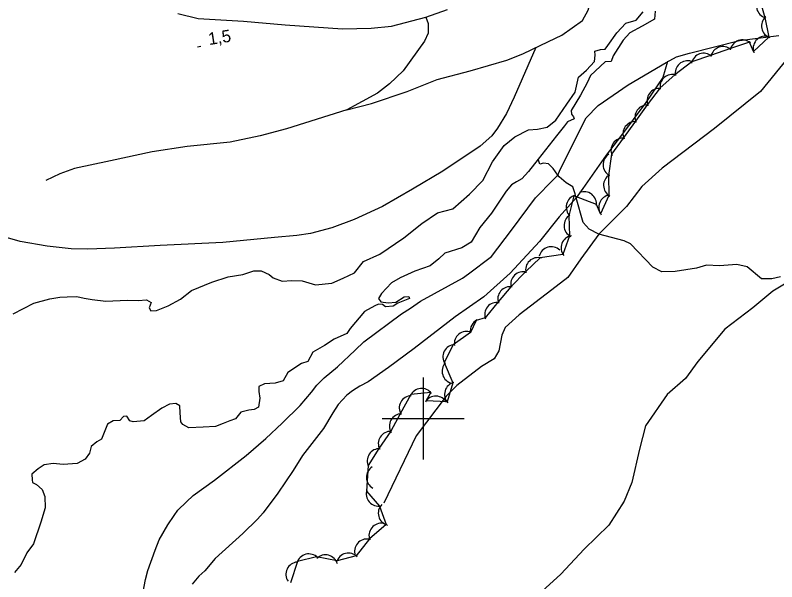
# Model space of a CAD drawing. Extents: x 643342 to 646936, y 5873857 to 5876103.
# Drawn here: x 644900.4 to 645086.4, y 5874560.2 to 5874698.4 of the extents above; entities that cross this region are included whole.
import ezdxf

# ---------------------------------------------------------------- set-up
doc = ezdxf.new("R2010")
doc.units = 0
for name, color, linetype in [('Niveau 2', 7, 'Continuous'), ('Niveau 22', 7, 'Continuous'), ('Niveau 3', 7, 'Continuous'), ('Niveau 4', 7, 'Continuous'), ('Niveau 44', 7, 'Continuous'), ('Niveau 61', 7, 'Continuous')]:
    doc.layers.add(name, color=color, linetype=linetype)

msp = doc.modelspace()

# ---------------------------------------------------------------- linework, layer by layer
at = {"layer": 'Niveau 2'}
for points in [[(645090.92, 5874634.41), (645085.43, 5874631.02), (645080.51, 5874627.01), (645073.66, 5874621.81), (645067.12, 5874613.9), (645064.04, 5874609.72), (645059.64, 5874605.87), (645054.32, 5874598.16), (645052.83, 5874592.48), (645050.96, 5874584.41), (645049.1, 5874579.78), (645045.36, 5874573.95), (645039.33, 5874568.09), (645033.6, 5874562.02)], [(645033.6, 5874562.02), (645028.16, 5874557.02), (645017.36, 5874550.84), (645003.58, 5874543.28), (644999.48, 5874539.32), (644990.35, 5874529.34), (644978.11, 5874518.31), (644963.38, 5874509.01), (644955.88, 5874501.15), (644949.79, 5874495.17), (644945.06, 5874485), (644942.13, 5874477.8), (644934.92, 5874462.37), (644928.86, 5874454.37), (644919.76, 5874449.01), (644910.52, 5874442.33), (644902.84, 5874436.11), (644893.32, 5874425.03), (644885.55, 5874412.64)]]:
    msp.add_lwpolyline(points, dxfattribs=at)
at = {"layer": 'Niveau 22'}
for points in [[(644981.35, 5874675.34), (644987.4, 5874676.81), (644996.09, 5874679.76), (645003.46, 5874682.74), (645011.49, 5874684.81), (645020.42, 5874687.42), (645024.34, 5874688.99), (645030.61, 5874691.98), (645033.85, 5874693.53), (645038.93, 5874697.08), (645040.29, 5874699.66), (645043.22, 5874710.44), (645044.35, 5874714.56)], [(644940.11, 5874698.83), (644945.06, 5874697.6), (644956.14, 5874696.9), (644966.28, 5874696.01), (644980.33, 5874695.03), (644987.31, 5874695.25), (644992.25, 5874695.69), (645000.63, 5874697.9), (645005.95, 5874699.8)], [(645000.63, 5874697.9), (645001.21, 5874696.39), (645001.25, 5874694.02), (645000.32, 5874692.05), (644995.14, 5874684.81), (644991.81, 5874681.62), (644988.88, 5874679.4), (644981.35, 5874675.34), (644966.62, 5874670.68), (644960.22, 5874668.96), (644952.86, 5874667.4), (644942.37, 5874666.35), (644933.8, 5874665.08), (644923.64, 5874662.86), (644914.87, 5874660.98), (644911.28, 5874659.67), (644907.84, 5874658.08)], [(645092.22, 5874694.56), (645088.79, 5874687.68), (645082.36, 5874679.78), (645071.16, 5874670.72), (645058.35, 5874661.09), (645053.45, 5874656.6), (645049.65, 5874651.72), (645042.92, 5874644.95), (645038.48, 5874638.96), (645035.37, 5874634.36), (645031.44, 5874631.36), (645023.46, 5874625.25), (645020.01, 5874622.17), (645019.19, 5874620.33), (645018.51, 5874616.49), (645017.34, 5874614.51), (645014.28, 5874612.64), (645008.2, 5874608.08), (645005.67, 5874605.41), (644998.28, 5874595.77), (644990.43, 5874579.33)], [(644937.65, 5874574.06), (644939.2, 5874576.29), (644940.07, 5874577.64), (644942.18, 5874579.62), (644943.83, 5874581.17), (644949.04, 5874584.91), (644956.82, 5874590.97), (644961.6, 5874595.12), (644965.58, 5874598.86), (644969.96, 5874603.18), (644972.75, 5874606.39), (644974.04, 5874608.12), (644975.85, 5874609.88), (644979.07, 5874612.6), (644983.39, 5874616.68), (644985.53, 5874618.72), (644994.74, 5874625.51), (644996.94, 5874626.91), (644999.35, 5874628.58), (645009.64, 5874634.23), (645011.09, 5874635.25), (645016.72, 5874639.54), (645021.6, 5874645.93), (645027.45, 5874653.81), (645031.76, 5874658.25), (645032.87, 5874659.4), (645033.3, 5874660.32), (645034.96, 5874663.64), (645039.85, 5874673.36), (645042.72, 5874676.4), (645050.07, 5874681.4), (645059.39, 5874686.89), (645061.9, 5874688.24), (645065.03, 5874689.16), (645077.23, 5874692.22), (645086.84, 5874693.44)], [(645027.55, 5874690.52), (645022.26, 5874678.41), (645020.33, 5874674.42), (645018.17, 5874670.81), (645016.75, 5874668.93), (645013.91, 5874666.44), (645004.8, 5874660.3), (644997.4, 5874655.97), (644990.09, 5874651.75), (644983.19, 5874648.54), (644977.67, 5874646.52), (644972.49, 5874645.12), (644969.19, 5874644.65), (644963.73, 5874644.13), (644951.05, 5874642.96), (644935.79, 5874642.18), (644924.64, 5874641.52), (644918.08, 5874641.31), (644914.04, 5874641.39), (644908.2, 5874642.02), (644901.63, 5874643.18), (644889.88, 5874646.5)], [(645059.72, 5874687.06), (645058.57, 5874683.18), (645054.38, 5874677.08), (645048.2, 5874668.83), (645044.74, 5874664.21), (645039.02, 5874656.1), (645037.41, 5874653.84), (645033.24, 5874649.16), (645028.45, 5874643.14), (645021.29, 5874635.41), (645014.82, 5874629.64), (645007.82, 5874624.77), (644997.8, 5874617.08), (644991.58, 5874612.43), (644986.6, 5874608.9), (644984.52, 5874607.9), (644982.74, 5874606.78), (644981.35, 5874605.69), (644979.22, 5874603.42), (644977.95, 5874601.4), (644975.65, 5874597.54), (644970.52, 5874590.96), (644968.25, 5874587.29), (644964.5, 5874581.8), (644960.9, 5874576.95), (644959.55, 5874575.42), (644955.99, 5874571.91), (644949.24, 5874565.83), (644946.73, 5874562.84), (644945.21, 5874561.49), (644943.59, 5874559.6)], [(644898.02, 5874498.92), (644900.58, 5874503.83), (644903.98, 5874509.35), (644906.78, 5874514.43), (644908.44, 5874517.12), (644909.89, 5874519.24), (644916.01, 5874526.45), (644920.84, 5874532.57), (644922.72, 5874534.87), (644927.21, 5874539.05), (644928.41, 5874540.13), (644928.79, 5874540.94), (644929.33, 5874542.75), (644929.86, 5874545.4), (644930.55, 5874549.19), (644931.23, 5874555.58), (644932.21, 5874560.72), (644932.77, 5874562.92), (644934.55, 5874567.88), (644935.58, 5874570.37), (644937.65, 5874574.06)]]:
    msp.add_lwpolyline(points, dxfattribs=at)
at = {"layer": 'Niveau 3'}
msp.add_line((644944.91, 5874690.69), (644945.7, 5874690.82), dxfattribs=at)
at = {"layer": 'Niveau 4'}
for points in [[(645056.65, 5874699.37), (645056.54, 5874697.46), (645053.46, 5874695.71), (645050.5, 5874694.09), (645048.84, 5874692.32), (645046.39, 5874688.47), (645045.89, 5874687.12), (645044.47, 5874687.03), (645040.91, 5874683.7), (645040.09, 5874681.87), (645038.4, 5874678.9), (645036.17, 5874675.18), (645036.24, 5874674.24), (645036.76, 5874673.56), (645036.91, 5874673.09), (645035.3, 5874672.39), (645034.54, 5874671.39), (645032.57, 5874669), (645028.12, 5874663.23), (645025.72, 5874660.22), (645024.07, 5874658.44), (645022.81, 5874657.77), (645021.56, 5874656.97), (645020.25, 5874655.46)], [(645041.93, 5874689.6), (645043.32, 5874690.05), (645044.5, 5874690.13), (645045.15, 5874691), (645047.3, 5874694.12), (645049.51, 5874696.41), (645052.06, 5874697.17), (645053.7, 5874699.18)], [(644899.92, 5874625.49), (644904.97, 5874628.09), (644908.81, 5874629.17), (644911.27, 5874629.58), (644913.05, 5874629.69), (644915.42, 5874629.73), (644917.23, 5874629.37), (644919.15, 5874629.02), (644922.5, 5874628.65), (644927.71, 5874628.88), (644930.44, 5874628.82), (644932.45, 5874628.95), (644933.56, 5874628.31), (644933.06, 5874626.97), (644933.47, 5874626.28), (644934.89, 5874626.37), (644937.77, 5874627.52), (644940.74, 5874629.14), (644943.45, 5874631.23), (644948.41, 5874633.22), (644952.35, 5874634.55), (644955.99, 5874635.15), (644958.65, 5874636.04), (644960.43, 5874636.04), (644962.4, 5874635.1), (644963.4, 5874634.33), (644965.59, 5874633.52), (644967.95, 5874633.68), (644970.45, 5874633.61), (644973.72, 5874632.63), (644977.72, 5874633.02), (644980.48, 5874634.27), (644983.24, 5874635.52), (644985.41, 5874638.28), (644989.44, 5874640.1), (644995.33, 5874644.06), (644999.7, 5874647.56), (645003.55, 5874650.19), (645007.28, 5874651.15), (645011.29, 5874654.75), (645014.62, 5874658.06), (645016.91, 5874662.61), (645019.83, 5874666.61), (645022.41, 5874668.69), (645025.72, 5874670.45), (645027.96, 5874670.6), (645030.3, 5874671.11), (645032.43, 5874672.8), (645035.12, 5874676.66), (645037.17, 5874679.65), (645037.98, 5874683.27), (645039.88, 5874684.95), (645041.86, 5874687.1), (645041.99, 5874688.65), (645041.93, 5874689.6)], [(645087.24, 5874634.59), (645085.15, 5874634.09), (645082.67, 5874634.05), (645079.16, 5874637.02), (645076.64, 5874637.56), (645072.41, 5874637.28), (645069.21, 5874637.43), (645066.78, 5874636.67), (645061.52, 5874635.85), (645058.33, 5874635.76), (645056.13, 5874636.92), (645050.65, 5874642.61), (645049.06, 5874643.34), (645042.92, 5874644.95), (645040.58, 5874646.22), (645039.06, 5874647.79), (645037.41, 5874653.84), (645037.15, 5874654.79), (645036.56, 5874656.54), (645034.95, 5874657.5), (645033.19, 5874658.93), (645032.87, 5874659.4), (645031.75, 5874660.98), (645030.61, 5874662.09), (645029.41, 5874662.25), (645028.48, 5874662.07), (645028.12, 5874663.23)], [(645020.25, 5874655.46), (645016.71, 5874650.11), (645013.87, 5874646.59), (645011.75, 5874643), (645009.48, 5874641.66), (645005.31, 5874640.29), (645003.87, 5874638.97), (645001.76, 5874637.24), (644997.95, 5874635.96), (644994.4, 5874634.34), (644992.25, 5874633.08), (644989.85, 5874630.49), (644989.12, 5874629.24), (644989.65, 5874628.45), (644991.44, 5874628.24), (644993.33, 5874628.41), (644995.36, 5874629.65), (644996.54, 5874629.76), (644996.69, 5874629.29), (644993.82, 5874628.09), (644992.69, 5874627.4), (644990.81, 5874627.24), (644990.06, 5874627.77), (644989.1, 5874627.92), (644988.19, 5874627.49), (644985.69, 5874626.08), (644982.22, 5874621.96), (644981.37, 5874620.7), (644978.28, 5874619.36), (644975.91, 5874617.84), (644973.08, 5874616.17), (644971.83, 5874613.91), (644970.33, 5874613.43), (644966.95, 5874611.23), (644965.8, 5874609.22), (644963.84, 5874608.58), (644961.24, 5874608.47), (644959.88, 5874607.76), (644959.85, 5874606.56), (644960.1, 5874604.92), (644959.78, 5874602.74), (644958.76, 5874602.18), (644957.47, 5874602.06), (644955.5, 5874601.54), (644954.2, 5874599.88), (644952.82, 5874599.4), (644951.21, 5874598.78), (644949.26, 5874598.02), (644946.31, 5874597.88), (644942.77, 5874597.7), (644941.28, 5874598.52), (644940.87, 5874599.2), (644940.7, 5874601.34), (644940.57, 5874603.11), (644939.58, 5874603.62), (644938.05, 5874603.49), (644936.23, 5874602.5), (644933.64, 5874600.73), (644931.86, 5874599.38), (644929.15, 5874599.15), (644928.41, 5874599.44), (644927.62, 5874600.57), (644926.79, 5874600.5), (644925.92, 5874599.47), (644924.27, 5874599.44)], [(644924.27, 5874599.44), (644922.91, 5874598.61), (644921.43, 5874594.91), (644920.29, 5874594.33), (644918.96, 5874593.14), (644918.49, 5874591.55), (644917.43, 5874590.03), (644915.49, 5874589.03), (644912.08, 5874588.74), (644909.69, 5874589.01), (644907.46, 5874588.7), (644906, 5874587.74), (644904.44, 5874586.41), (644904.56, 5874584.99), (644904.6, 5874584.4), (644905.59, 5874583.89), (644906.99, 5874582.7), (644907.6, 5874580.96), (644907.7, 5874578.23), (644906.67, 5874574.68), (644904.84, 5874569.4), (644903.23, 5874567.23), (644901.8, 5874564.37), (644900.18, 5874562.44)]]:
    msp.add_lwpolyline(points, dxfattribs=at)
at = {"layer": 'Niveau 44'}
msp.add_lwpolyline([(645082.06, 5874702.74), (645083.43, 5874697.8), (645084.39, 5874693.04), (645080.69, 5874689.54), (645079.67, 5874691.83), (645075.08, 5874690.25), (645070.22, 5874688.57), (645065.63, 5874687), (645061.49, 5874683.88), (645057.87, 5874680.64), (645054.74, 5874676.5), (645051.89, 5874672.57), (645048.87, 5874668.4), (645046.02, 5874664.47), (645045.24, 5874659.29), (645045.35, 5874654.43), (645043.34, 5874649.94), (645042.33, 5874652.24), (645036.82, 5874654.35), (645035.55, 5874649.42), (645035.78, 5874644.57), (645034.15, 5874640), (645028.57, 5874639.19), (645025.06, 5874635.84), (645021.44, 5874632.14), (645018.33, 5874628.42), (645015.12, 5874624.58), (645012.95, 5874623.93), (645011.54, 5874620.98), (645007.36, 5874617.98), (645005.15, 5874613.66), (645007.24, 5874608.7), (645005.84, 5874604.05), (645000.72, 5874604.27), (645001.86, 5874606.33), (644997.04, 5874605.83), (644994.4, 5874601.14), (644992.08, 5874596.88), (644989.19, 5874592.64), (644986.56, 5874588.55), (644986.16, 5874582.26), (644989.38, 5874578.63), (644990.98, 5874574.1), (644986.89, 5874570.64), (644983.69, 5874566.44), (644978.98, 5874565.28), (644974, 5874566.25), (644969.29, 5874565.07), (644967.63, 5874559.89)], dxfattribs=at)
for centre, start, end in [((645084.39, 5874700.7), 134.9289, 254.9068), ((645084.39, 5874700.7), 134.9289, 254.9068), ((645084.39, 5874700.7), 134.9289, 254.9068), ((645085.64, 5874695.76), 131.3422, 251.3202), ((645085.64, 5874695.76), 131.3422, 251.3202), ((645085.64, 5874695.76), 131.3422, 251.3202), ((645077.95, 5874689.37), 48.9917, 168.9697), ((645077.95, 5874689.37), 48.9917, 168.9697), ((645077.95, 5874689.37), 48.9917, 168.9697), ((645083.6, 5874690.29), 80.4959, 200.4738), ((645083.6, 5874690.29), 80.4959, 200.4738), ((645083.6, 5874690.29), 80.4959, 200.4738), ((645073.22, 5874687.74), 48.9917, 168.9697), ((645073.22, 5874687.74), 48.9917, 168.9697), ((645073.22, 5874687.74), 48.9917, 168.9697), ((645068.5, 5874686.12), 48.9917, 168.9697), ((645068.5, 5874686.12), 48.9917, 168.9697), ((645068.5, 5874686.12), 48.9917, 168.9697), ((645064.58, 5874684.28), 71.868, 191.846), ((645064.58, 5874684.28), 71.868, 191.846), ((645064.58, 5874684.28), 71.868, 191.846), ((645060.86, 5874680.94), 71.868, 191.846), ((645060.86, 5874680.94), 71.868, 191.846), ((645060.86, 5874680.94), 71.868, 191.846), ((645057.68, 5874677.55), 84.0782, 204.0562), ((645057.68, 5874677.55), 84.0782, 204.0562), ((645057.68, 5874677.55), 84.0782, 204.0562), ((645054.74, 5874673.5), 84.0782, 204.0562), ((645054.74, 5874673.5), 84.0782, 204.0562), ((645054.74, 5874673.5), 84.0782, 204.0562), ((645051.81, 5874669.45), 84.0782, 204.0562), ((645051.81, 5874669.45), 84.0782, 204.0562), ((645051.81, 5874669.45), 84.0782, 204.0562), ((645048.87, 5874665.4), 84.0782, 204.0562), ((645048.87, 5874665.4), 84.0782, 204.0562), ((645048.87, 5874665.4), 84.0782, 204.0562), ((645046.95, 5874661.9), 121.3045, 241.2825), ((645046.95, 5874661.9), 121.3045, 241.2825), ((645046.95, 5874661.9), 121.3045, 241.2825), ((645047.06, 5874656.9), 121.3045, 241.2825), ((645047.06, 5874656.9), 121.3045, 241.2825), ((645047.06, 5874656.9), 121.3045, 241.2825), ((645039.34, 5874652.33), 352.2444, 112.2224), ((645039.34, 5874652.33), 352.2444, 112.2224), ((645039.34, 5874652.33), 352.2444, 112.2224), ((645037.95, 5874651.57), 106.1625, 226.1404), ((645037.95, 5874651.57), 106.1625, 226.1404), ((645037.95, 5874651.57), 106.1625, 226.1404), ((645045.89, 5874651.51), 97.4842, 217.4622), ((645045.89, 5874651.51), 97.4842, 217.4622), ((645045.89, 5874651.51), 97.4842, 217.4622), ((645037.42, 5874647.08), 122.6548, 242.6328), ((645037.42, 5874647.08), 122.6548, 242.6328), ((645037.42, 5874647.08), 122.6548, 242.6328), ((645036.68, 5874641.61), 98.5863, 218.5643), ((645036.68, 5874641.61), 98.5863, 218.5643), ((645036.68, 5874641.61), 98.5863, 218.5643), ((645031.28, 5874638.9), 46.3938, 166.3718), ((645031.28, 5874638.9), 46.3938, 166.3718), ((645031.28, 5874638.9), 46.3938, 166.3718), ((645028.03, 5874636.24), 73.7217, 193.6997), ((645028.03, 5874636.24), 73.7217, 193.6997), ((645028.03, 5874636.24), 73.7217, 193.6997), ((645024.42, 5874632.79), 73.7217, 193.6997), ((645024.42, 5874632.79), 73.7217, 193.6997), ((645024.42, 5874632.79), 73.7217, 193.6997), ((645021.24, 5874629.15), 80.106, 200.084), ((645021.24, 5874629.15), 80.106, 200.084), ((645021.24, 5874629.15), 80.106, 200.084), ((645018.03, 5874625.32), 80.106, 200.084), ((645018.03, 5874625.32), 80.106, 200.084), ((645018.03, 5874625.32), 80.106, 200.084), ((645014.51, 5874621.37), 115.4847, 188.7569), ((645014.51, 5874621.37), 115.4847, 188.7569), ((645014.51, 5874621.37), 115.4847, 188.7569), ((645010.61, 5874618.24), 68.7789, 188.7569), ((645010.61, 5874618.24), 68.7789, 188.7569), ((645010.61, 5874618.24), 68.7789, 188.7569), ((645007.83, 5874615.01), 92.8318, 212.8097), ((645007.83, 5874615.01), 92.8318, 212.8097), ((645007.83, 5874615.01), 92.8318, 212.8097), ((645007.64, 5874611.53), 137.4321, 257.41), ((645007.64, 5874611.53), 137.4321, 257.41), ((645007.64, 5874611.53), 137.4321, 257.41), ((645008.23, 5874605.87), 103.2772, 223.2552), ((645008.23, 5874605.87), 103.2772, 223.2552), ((645008.23, 5874605.87), 103.2772, 223.2552), ((644999.63, 5874604.33), 35.8768, 155.8547), ((644999.63, 5874604.33), 35.8768, 155.8547), ((644999.63, 5874604.33), 35.8768, 155.8547), ((644997.17, 5874602.56), 91.514, 211.4919), ((644997.17, 5874602.56), 91.514, 211.4919), ((644997.17, 5874602.56), 91.514, 211.4919), ((645003.1, 5874602.44), 28.3569, 148.3348), ((645003.1, 5874602.44), 28.3569, 148.3348), ((645003.1, 5874602.44), 28.3569, 148.3348), ((644994.79, 5874598.17), 91.514, 211.4919), ((644994.79, 5874598.17), 91.514, 211.4919), ((644994.79, 5874598.17), 91.514, 211.4919), ((644992.06, 5874593.85), 87.3019, 207.2798), ((644992.06, 5874593.85), 87.3019, 207.2798), ((644992.06, 5874593.85), 87.3019, 207.2798), ((644989.36, 5874589.64), 87.3019, 207.2798), ((644989.36, 5874589.64), 87.3019, 207.2798), ((644989.36, 5874589.64), 87.3019, 207.2798), ((644989.16, 5874585.65), 121.4135, 241.3915), ((644989.16, 5874585.65), 121.4135, 241.3915), ((644989.16, 5874585.65), 121.4135, 241.3915), ((644989.09, 5874581.62), 161.5434, 281.5214), ((644989.09, 5874581.62), 161.5434, 281.5214), ((644989.09, 5874581.62), 161.5434, 281.5214), ((644992.04, 5874576.9), 135.272, 255.2499), ((644992.04, 5874576.9), 135.272, 255.2499), ((644992.04, 5874576.9), 135.272, 255.2499), ((644989.78, 5874571.43), 81.204, 201.1819), ((644989.78, 5874571.43), 81.204, 201.1819), ((644989.78, 5874571.43), 81.204, 201.1819), ((644986.26, 5874567.59), 72.3355, 192.3134), ((644986.26, 5874567.59), 72.3355, 192.3134), ((644986.26, 5874567.59), 72.3355, 192.3134), ((644972.07, 5874563.95), 44.0609, 164.0388), ((644972.07, 5874563.95), 44.0609, 164.0388), ((644972.07, 5874563.95), 44.0609, 164.0388), ((644976.17, 5874563.72), 15.3762, 135.3541), ((644976.17, 5874563.72), 15.3762, 135.3541), ((644976.17, 5874563.72), 15.3762, 135.3541), ((644981.76, 5874564.15), 43.8939, 163.8718), ((644981.76, 5874564.15), 43.8939, 163.8718), ((644981.76, 5874564.15), 43.8939, 163.8718), ((644969.5, 5874561.97), 94.4269, 214.4048), ((644969.5, 5874561.97), 94.4269, 214.4048), ((644969.5, 5874561.97), 94.4269, 214.4048)]:
    msp.add_arc(centre, 3, start, end, dxfattribs=at)
at = {"layer": 'Niveau 61'}
for points in [[(645000, 5874610), (645000, 5874600), (645000, 5874590)], [(644990, 5874600), (645000, 5874600), (645010, 5874600)]]:
    msp.add_lwpolyline(points, dxfattribs=at)

# ---------------------------------------------------------------- texts
at = {"layer": 'Niveau 3'}
msp.add_text('1,5  ', height=3, rotation=8.9405, dxfattribs=at).set_placement((644947.76, 5874691.1))

doc.saveas('drawing.dxf')
